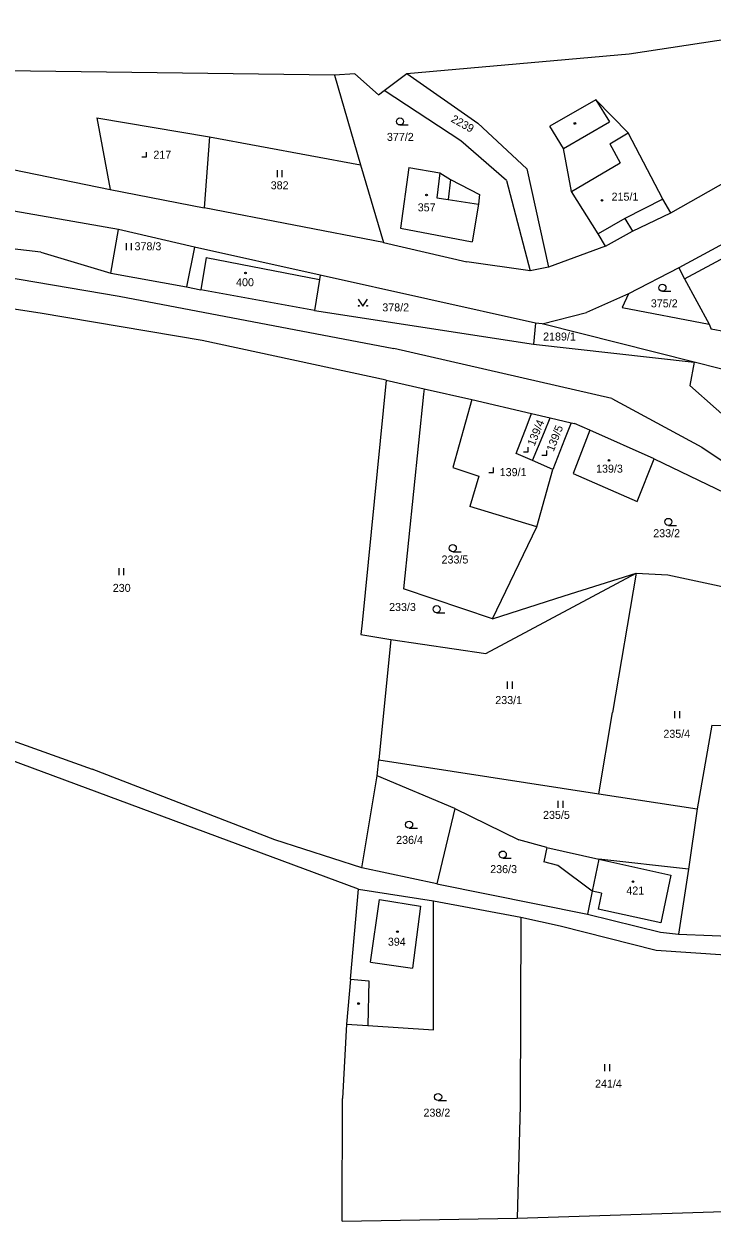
# Model space of a CAD drawing. Extents: x -717507 to -715515, y -957700 to -954941.
# Drawn here: x -717347.3 to -717201.2, y -957639.5 to -957385.3 of the extents above; entities that cross this region are included whole.
import ezdxf

# ---------------------------------------------------------------- set-up
doc = ezdxf.new("R2010")
doc.units = 0
for name, color, linetype in [('Hranice parcel', 7, 'Continuous'), ('Parcelní čísla', 7, 'Continuous'), ('Vnitřní kresba', 7, 'Continuous'), ('Značky budov', 7, 'Continuous'), ('Značky kultur', 7, 'Continuous')]:
    doc.layers.add(name, color=color, linetype=linetype)

msp = doc.modelspace()

# ---------------------------------------------------------------- linework, layer by layer
at = {"layer": 'Hranice parcel'}
for points in [[(-717209.93, -957425.39), (-717099.07, -957362.51)], [(-717218.75, -957391.65), (-717184.82, -957386.45)], [(-717265.97, -957395.79), (-717218.75, -957391.65)], [(-717281.33, -957396.16), (-717351.24, -957395.25)], [(-717276.99, -957395.86), (-717281.33, -957396.16)], [(-717281.33, -957396.16), (-717275.83, -957415.22)], [(-717276.99, -957395.86), (-717271.99, -957400.32)], [(-717270.8, -957399.39), (-717265.97, -957395.79)], [(-717265.97, -957395.79), (-717250.89, -957406.35)], [(-717271.99, -957400.32), (-717270.8, -957399.39)], [(-717254.55, -957410.08), (-717270.8, -957399.39)], [(-717225.82, -957401.41), (-717235.65, -957406.96)], [(-717225.82, -957401.41), (-717218.96, -957408.42)], [(-717331.82, -957405.2), (-717328.95, -957420.41)], [(-717331.82, -957405.2), (-717307.87, -957409.23)], [(-717240.51, -957416.06), (-717250.89, -957406.35)], [(-717232.72, -957411.73), (-717235.65, -957406.96)], [(-717307.87, -957409.23), (-717309.03, -957424.32)], [(-717307.87, -957409.23), (-717275.83, -957415.22)], [(-717244.85, -957418.51), (-717254.55, -957410.08)], [(-717211.63, -957422.5), (-717218.96, -957408.42)], [(-717231.01, -957420.83), (-717232.72, -957411.73)], [(-717355.88, -957414.91), (-717347.27, -957416.68)], [(-717275.83, -957415.22), (-717270.95, -957431.71)], [(-717265.54, -957415.76), (-717267.31, -957428.64)], [(-717265.54, -957415.76), (-717259.01, -957416.86)], [(-717347.27, -957416.68), (-717328.95, -957420.41)], [(-717259.01, -957416.86), (-717256.69, -957418.32)], [(-717240.51, -957416.06), (-717235.93, -957436.89)], [(-717328.95, -957420.41), (-717309.03, -957424.32)], [(-717256.69, -957418.32), (-717250.53, -957421.5)], [(-717244.85, -957418.51), (-717239.77, -957437.68)], [(-717225.33, -957429.86), (-717231.01, -957420.83)], [(-717250.53, -957421.5), (-717250.77, -957423.57)], [(-717209.93, -957425.39), (-717211.63, -957422.5)], [(-717327.24, -957428.93), (-717353.56, -957424.35)], [(-717270.95, -957431.71), (-717309.03, -957424.32)], [(-717250.77, -957423.57), (-717252.11, -957431.51)], [(-717218.06, -957429.31), (-717209.93, -957425.39)], [(-717190.05, -957427.2), (-717208.25, -957437.04)], [(-717343.67, -957433.75), (-717374.78, -957430.09)], [(-717328.83, -957438.21), (-717327.24, -957428.93)], [(-717311.09, -957432.65), (-717327.24, -957428.93)], [(-717267.31, -957428.64), (-717252.11, -957431.51)], [(-717223.8, -957432.43), (-717225.33, -957429.86)], [(-717223.8, -957432.43), (-717218.06, -957429.31)], [(-717311.09, -957432.65), (-717312.8, -957441.08)], [(-717284.41, -957438.64), (-717311.09, -957432.65)], [(-717270.95, -957431.71), (-717253.26, -957435.79)], [(-717223.8, -957432.43), (-717235.93, -957436.89)], [(-717343.67, -957433.75), (-717328.83, -957438.21)], [(-717239.77, -957437.68), (-717253.26, -957435.79)], [(-717362.54, -957437.07), (-717327.07, -957443.06)], [(-717328.83, -957438.21), (-717312.8, -957441.08)], [(-717235.93, -957436.89), (-717239.77, -957437.68)], [(-717208.25, -957437.04), (-717218.93, -957442.59)], [(-717208.25, -957437.04), (-717207.03, -957439.37)], [(-717312.8, -957441.08), (-717309.69, -957441.75)], [(-717284.56, -957439.51), (-717285.57, -957446.09)], [(-717284.41, -957438.64), (-717284.56, -957439.51)], [(-717238.69, -957448.78), (-717284.41, -957438.64)], [(-717207.03, -957439.37), (-717201.79, -957449.02)], [(-717327.07, -957443.06), (-717268.73, -957454.21)], [(-717285.57, -957446.09), (-717309.69, -957441.75)], [(-717218.93, -957442.59), (-717227.82, -957446.58)], [(-717218.93, -957442.59), (-717220.23, -957445.47)], [(-717343.83, -957446.67), (-717363.3, -957443.73)], [(-717285.57, -957446.09), (-717239.06, -957453.24)], [(-717220.23, -957445.47), (-717201.79, -957449.02)], [(-717309.41, -957452.49), (-717343.83, -957446.67)], [(-717238.69, -957448.78), (-717239.06, -957453.24)], [(-717237.22, -957448.96), (-717238.69, -957448.78)], [(-717237.22, -957448.96), (-717227.82, -957446.58)], [(-717205, -957457.07), (-717237.22, -957448.96)], [(-717201.79, -957449.02), (-717201.36, -957450.06)], [(-717198.31, -957450.67), (-717201.36, -957450.06)], [(-717270.4, -957460.9), (-717309.41, -957452.49)], [(-717239.06, -957453.24), (-717205, -957457.07)], [(-717222.48, -957464.83), (-717268.73, -957454.21)], [(-717205, -957457.07), (-717205.86, -957462.08)], [(-717193.77, -957459.92), (-717205, -957457.07)], [(-717270.4, -957460.9), (-717275.48, -957512.44)], [(-717270.4, -957460.9), (-717262.3, -957462.73)], [(-717262.42, -957463.85), (-717266.72, -957505.25)], [(-717262.3, -957462.73), (-717262.42, -957463.85)], [(-717262.3, -957462.73), (-717252.17, -957465.03)], [(-717205.86, -957462.08), (-717194.69, -957471.98)], [(-717252.17, -957465.03), (-717256.2, -957479.44)], [(-717252.17, -957465.03), (-717239.51, -957467.98)], [(-717222.48, -957464.83), (-717203.32, -957475.14)], [(-717240.44, -957470.44), (-717239.51, -957467.98)], [(-717239.51, -957467.98), (-717235.57, -957468.9)], [(-717236.78, -957471.86), (-717235.57, -957468.9)], [(-717235.57, -957468.9), (-717231.11, -957469.94)], [(-717242.77, -957476.49), (-717240.44, -957470.44)], [(-717231.11, -957469.94), (-717232.5, -957473.51)], [(-717231.11, -957469.94), (-717230.35, -957470.12)], [(-717227.11, -957471.51), (-717230.69, -957480.73)], [(-717227.11, -957471.51), (-717230.35, -957470.12)], [(-717213.48, -957477.61), (-717227.11, -957471.51)], [(-717239.29, -957477.99), (-717236.78, -957471.86)], [(-717232.5, -957473.51), (-717234.95, -957479.85)], [(-717239.29, -957477.99), (-717242.77, -957476.49)], [(-717203.32, -957475.14), (-717194.9, -957480.82)], [(-717234.95, -957479.85), (-717239.29, -957477.99)], [(-717217.06, -957486.65), (-717213.48, -957477.61)], [(-717213.48, -957477.61), (-717185.38, -957491.11)], [(-717256.2, -957479.44), (-717250.71, -957481.27)], [(-717250.71, -957481.27), (-717252.63, -957487.72)], [(-717238.41, -957492.08), (-717234.95, -957479.85)], [(-717230.69, -957480.73), (-717217.06, -957486.65)], [(-717238.41, -957492.08), (-717252.63, -957487.72)], [(-717247.79, -957511.57), (-717238.41, -957492.08)], [(-717249.19, -957518.98), (-717217.26, -957501.87)], [(-717232.57, -957506.74), (-717217.26, -957501.87)], [(-717217.26, -957501.87), (-717222.33, -957531.49)], [(-717217.26, -957501.87), (-717210.55, -957502.23)], [(-717210.55, -957502.23), (-717189.11, -957506.88)], [(-717247.79, -957511.57), (-717266.72, -957505.25)], [(-717247.79, -957511.57), (-717232.57, -957506.74)], [(-717275.48, -957512.44), (-717275.72, -957514.92)], [(-717275.72, -957514.92), (-717269.35, -957515.96)], [(-717269.35, -957515.96), (-717271.92, -957541.54)], [(-717269.35, -957515.96), (-717249.19, -957518.98)], [(-717373.17, -957529.1), (-717332.79, -957543.5)], [(-717225.22, -957548.72), (-717222.33, -957531.49)], [(-717201.19, -957534.18), (-717204.36, -957551.92)], [(-717201.19, -957534.18), (-717180.07, -957534.67)], [(-717276.27, -957569.02), (-717361.78, -957537.27)], [(-717272.26, -957544.9), (-717271.92, -957541.54)], [(-717271.92, -957541.54), (-717225.22, -957548.72)], [(-717294.03, -957558.49), (-717332.79, -957543.5)], [(-717275.57, -957564.46), (-717272.26, -957544.9)], [(-717255.78, -957551.86), (-717272.26, -957544.9)], [(-717225.22, -957548.72), (-717204.36, -957551.92)], [(-717255.78, -957551.86), (-717259.63, -957567.85)], [(-717255.78, -957551.86), (-717242.19, -957558.52)], [(-717204.36, -957551.92), (-717206.14, -957564.77)], [(-717275.57, -957564.46), (-717294.03, -957558.49)], [(-717236.22, -957560.13), (-717242.19, -957558.52)], [(-717236.22, -957560.13), (-717236.92, -957563.21)], [(-717236.22, -957560.13), (-717225.2, -957562.62)], [(-717206.14, -957564.77), (-717225.2, -957562.62)], [(-717259.63, -957567.85), (-717275.57, -957564.46)], [(-717233.93, -957563.94), (-717236.92, -957563.21)], [(-717226.6, -957569.4), (-717233.93, -957563.94)], [(-717206.14, -957564.77), (-717208.28, -957578.53)], [(-717259.63, -957567.85), (-717227.65, -957574.29)], [(-717277.91, -957588.13), (-717276.27, -957569.02)], [(-717276.27, -957569.02), (-717260.33, -957571.46)], [(-717226.6, -957569.4), (-717227.65, -957574.29)], [(-717260.33, -957598.87), (-717260.33, -957571.46)], [(-717260.33, -957571.46), (-717241.77, -957574.95)], [(-717241.77, -957574.95), (-717241.91, -957615.01)], [(-717241.77, -957574.95), (-717233.45, -957576.77)], [(-717227.65, -957574.29), (-717212.12, -957578.14)], [(-717233.45, -957576.77), (-717213.06, -957581.96)], [(-717212.12, -957578.14), (-717208.28, -957578.53)], [(-717208.28, -957578.53), (-717165.38, -957580.26)], [(-717213.06, -957581.96), (-717198.35, -957582.94)], [(-717277.91, -957588.13), (-717278.76, -957597.65)], [(-717278.76, -957597.65), (-717279.61, -957613.43)], [(-717278.76, -957597.65), (-717274.25, -957597.96)], [(-717274.25, -957597.96), (-717260.33, -957598.87)], [(-717279.74, -957639.46), (-717279.61, -957613.43)], [(-717241.91, -957615.01), (-717242.58, -957638.84)], [(-717279.74, -957639.46), (-717242.58, -957638.84)], [(-717242.58, -957638.84), (-717198.7, -957637.41)]]:
    msp.add_lwpolyline(points, dxfattribs=at)
at = {"layer": 'Vnitřní kresba'}
for points in [[(-717225.82, -957401.41), (-717222.95, -957406.05)], [(-717232.72, -957411.73), (-717222.95, -957406.05)], [(-717222.89, -957410.75), (-717218.96, -957408.42)], [(-717222.89, -957410.75), (-717220.69, -957414.78)], [(-717231.01, -957420.83), (-717220.69, -957414.78)], [(-717259.01, -957416.86), (-717259.62, -957422.17)], [(-717256.69, -957418.32), (-717257.18, -957422.54)], [(-717259.62, -957422.17), (-717257.18, -957422.54)], [(-717257.18, -957422.54), (-717250.77, -957423.57)], [(-717211.63, -957422.5), (-717219.71, -957426.57)], [(-717219.71, -957426.57), (-717225.33, -957429.86)], [(-717219.71, -957426.57), (-717218.06, -957429.31)], [(-717207.03, -957439.37), (-717188.68, -957429.59)], [(-717308.59, -957434.85), (-717309.69, -957441.75)], [(-717308.59, -957434.85), (-717284.56, -957439.51)], [(-717225.2, -957562.62), (-717226.6, -957569.4)], [(-717225.2, -957562.62), (-717209.94, -957566.04)], [(-717209.94, -957566.04), (-717212.08, -957576.15)], [(-717224.63, -957569.85), (-717226.6, -957569.4)], [(-717224.63, -957569.85), (-717225.34, -957573.26)], [(-717273.67, -957584.5), (-717271.78, -957571.18)], [(-717271.78, -957571.18), (-717263.09, -957572.57)], [(-717263.09, -957572.57), (-717264.77, -957585.74)], [(-717212.08, -957576.15), (-717225.34, -957573.26)], [(-717273.67, -957584.5), (-717264.77, -957585.74)], [(-717277.91, -957588.13), (-717274.06, -957588.43)], [(-717274.06, -957588.43), (-717274.25, -957597.96)]]:
    msp.add_lwpolyline(points, dxfattribs=at)
at = {"layer": 'Značky budov'}
for centre in [(-717261.8, -957421.61), (-717224.54, -957422.73), (-717300.24, -957438.17), (-717223.05, -957477.96), (-717217.97, -957567.38), (-717267.97, -957578), (-717276.24, -957593.27)]:
    msp.add_circle(centre, 0.175, dxfattribs=at)
at = {"layer": 'Značky kultur'}
for points in [[(-717267.44, -957406.73), (-717265.69, -957406.73)], [(-717322.24, -957413.48), (-717321.24, -957413.48), (-717321.24, -957412.48)], [(-717293.48, -957417.8), (-717293.48, -957416.3)], [(-717292.44, -957417.8), (-717292.44, -957416.3)], [(-717325.52, -957433.3), (-717325.52, -957431.8)], [(-717324.48, -957433.3), (-717324.48, -957431.8)], [(-717211.71, -957442.05), (-717209.96, -957442.05)], [(-717276.3, -957443.73), (-717275.3, -957445.23), (-717274.3, -957443.73)], [(-717241.23, -957476.13), (-717240.23, -957476.13), (-717240.23, -957475.13)], [(-717237.29, -957476.87), (-717236.29, -957476.87), (-717236.29, -957475.87)], [(-717248.59, -957480.49), (-717247.59, -957480.49), (-717247.59, -957479.49)], [(-717210.45, -957491.76), (-717208.7, -957491.76)], [(-717256.23, -957497.33), (-717254.48, -957497.33)], [(-717327.1, -957502.33), (-717327.1, -957500.83)], [(-717326.06, -957502.33), (-717326.06, -957500.83)], [(-717259.65, -957510.29), (-717257.9, -957510.29)], [(-717244.62, -957526.42), (-717244.62, -957524.92)], [(-717243.58, -957526.42), (-717243.58, -957524.92)], [(-717209.06, -957532.71), (-717209.06, -957531.21)], [(-717208.02, -957532.71), (-717208.02, -957531.21)], [(-717233.84, -957551.72), (-717233.84, -957550.22)], [(-717232.8, -957551.72), (-717232.8, -957550.22)], [(-717265.5, -957556.05), (-717263.75, -957556.05)], [(-717245.61, -957562.39), (-717243.86, -957562.39)], [(-717223.92, -957607.65), (-717223.92, -957606.15)], [(-717222.88, -957607.65), (-717222.88, -957606.15)], [(-717259.33, -957613.86), (-717257.58, -957613.86)]]:
    msp.add_lwpolyline(points, dxfattribs=at)
for centre, radius in [((-717267.44, -957405.98), 0.75), ((-717230.3, -957406.4), 0.175), ((-717211.71, -957441.3), 0.75), ((-717276.2, -957445.13), 0.1), ((-717274.4, -957445.13), 0.1), ((-717210.45, -957491.01), 0.75), ((-717256.23, -957496.58), 0.75), ((-717259.65, -957509.54), 0.75), ((-717265.5, -957555.3), 0.75), ((-717245.61, -957561.64), 0.75), ((-717259.33, -957613.11), 0.75)]:
    msp.add_circle(centre, radius, dxfattribs=at)

# ---------------------------------------------------------------- texts
at = {"layer": 'Parcelní čísla'}
for s, rotation, p in [('2239', 330.7026, (-717256.76, -957405.94)), ('139/4', 67.7005, (-717238.89, -957475.03)), ('139/5', 68.8005, (-717234.81, -957476.2))]:
    msp.add_text(s, height=1.7, rotation=rotation, dxfattribs=at).set_placement(p)
for s, p in [('377/2', (-717270.21, -957410.11)), ('217', (-717319.8, -957413.89)), ('382', (-717294.89, -957420.38)), ('357', (-717263.67, -957425.07)), ('215/1', (-717222.51, -957422.8)), ('378/3', (-717323.8, -957433.33)), ('400', (-717302.24, -957440.96)), ('375/2', (-717214.17, -957445.45)), ('378/2', (-717271.19, -957446.31)), ('2189/1', (-717237.05, -957452.5)), ('139/3', (-717225.8, -957480.55)), ('139/1', (-717246.26, -957481.29)), ('233/2', (-717213.66, -957494.26)), ('233/5', (-717258.61, -957499.84)), ('230', (-717328.42, -957505.87)), ('233/3', (-717269.75, -957509.93)), ('233/1', (-717247.2, -957529.69)), ('235/4', (-717211.51, -957536.85)), ('235/5', (-717237.06, -957554.07)), ('236/4', (-717268.25, -957559.37)), ('236/3', (-717248.28, -957565.58)), ('421', (-717219.37, -957570.13)), ('394', (-717270.01, -957581)), ('241/4', (-717226.02, -957611.14)), ('238/2', (-717262.45, -957617.29))]:
    msp.add_text(s, height=1.7, dxfattribs=at).set_placement(p)

doc.saveas('drawing.dxf')
